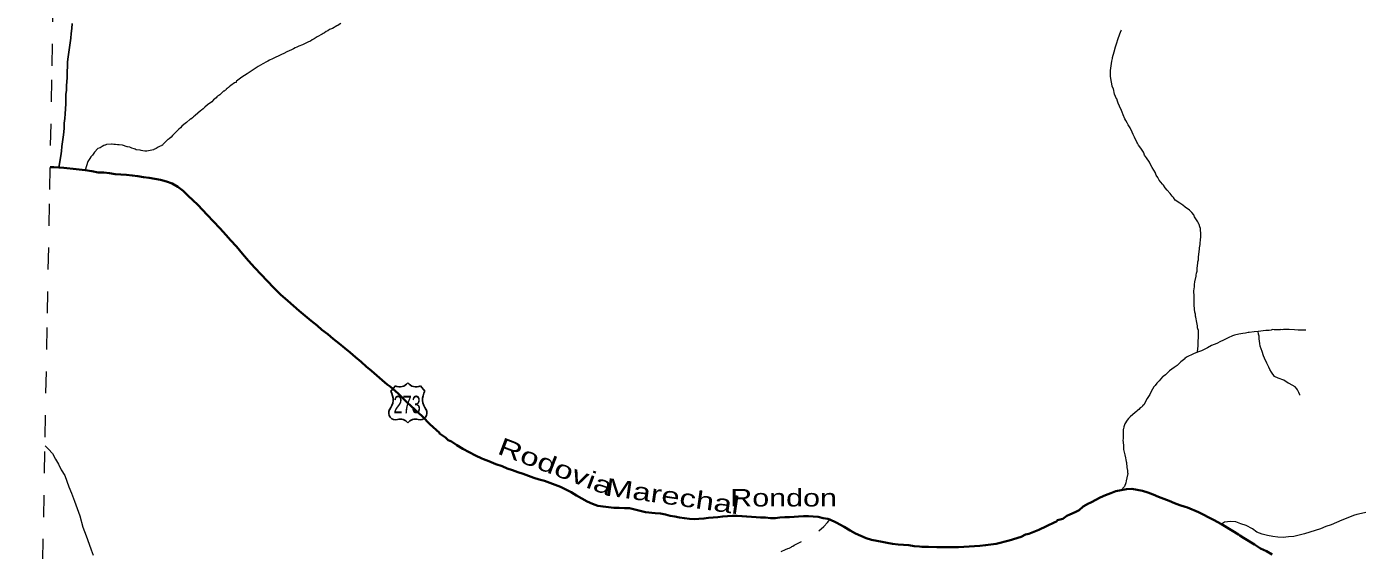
# Model space of a CAD drawing. Extents: x 781.9 to 808.1, y 7453.3 to 7481.5.
# Drawn here: x 781.91 to 787.99, y 7457.81 to 7460.2 of the extents above; entities that cross this region are included whole.
import ezdxf
from ezdxf.enums import TextEntityAlignment as Align

# ---------------------------------------------------------------- set-up
doc = ezdxf.new("R2010")
doc.units = 0
doc.header["$LTSCALE"] = 0.032
for name, pattern in [('DOTTED', [1.5, 0.3, -1.2]), ('LONG_DASHED', [7.5, 6, -1.5]), ('SHORT_DASHED', [2.7, 1.5, -1.2])]:
    doc.linetypes.add(name, pattern=pattern)
for name, color, linetype, lineweight in [('12', 7, 'Continuous', 25), ('2', 7, 'Continuous', 35), ('35', 7, 'SHORT_DASHED', 13), ('4', 7, 'LONG_DASHED', 25), ('5', 7, 'LONG_DASHED', 13), ('7', 7, 'DOTTED', 13)]:
    doc.layers.add(name, color=color, linetype=linetype, lineweight=lineweight)
doc.layers.add('61', color=7, linetype='Continuous')

msp = doc.modelspace()

# ---------------------------------------------------------------- linework, layer by layer
at = {"layer": '12'}
for p, q in [((783.5758, 7458.5342), (783.5967, 7458.5585)), ((783.5758, 7458.5342), (783.5967, 7458.5585)), ((783.6538, 7458.5716), (783.6542, 7458.5712)), ((783.6538, 7458.5716), (783.6542, 7458.5712)), ((783.711, 7458.5585), (783.7319, 7458.5345)), ((783.711, 7458.5585), (783.7319, 7458.5345))]:
    msp.add_line(p, q, dxfattribs=at)
for centre, radius, start, end in [((783.6175, 7458.5986), 0.0452, 242.52866, 323.41613), ((783.6175, 7458.5986), 0.0452, 242.52866, 323.41613), ((783.6901, 7458.5986), 0.0452, 217.23651, 297.49117), ((783.6901, 7458.5986), 0.0452, 217.23651, 297.49117), ((783.5126, 7458.496), 0.0738, 320.67544, 31.14191), ((783.5126, 7458.496), 0.0738, 320.67544, 31.14191), ((783.795, 7458.496), 0.0738, 148.68696, 219.32477), ((783.795, 7458.496), 0.0738, 148.68696, 219.32477), ((783.5978, 7458.4344), 0.0316, 151.50035, 286.50661), ((783.5978, 7458.4344), 0.0316, 151.50035, 286.50661), ((783.7099, 7458.4344), 0.0316, 253.49417, 28.49965), ((783.7099, 7458.4344), 0.0316, 253.49417, 28.49965), ((783.6198, 7458.3627), 0.0433, 38.34716, 107.68663), ((783.6198, 7458.3627), 0.0433, 38.34716, 107.68663), ((783.6878, 7458.3627), 0.0433, 72.31281, 141.65284), ((783.6878, 7458.3627), 0.0433, 72.31281, 141.65284)]:
    msp.add_arc(centre, radius, start, end, dxfattribs=at)
at = {"layer": '2'}
msp.add_line((786.8894, 7458.0772), (786.9137, 7458.082), dxfattribs=at)
for points in [[(782.0194, 7459.5565), (782.0367, 7459.5559), (782.059, 7459.5551)], [(782.059, 7459.5551), (782.0824, 7459.5527), (782.1377, 7459.5471), (782.1794, 7459.5423)], [(782.1794, 7459.5423), (782.2098, 7459.5375), (782.2389, 7459.5325), (782.2648, 7459.5317), (782.2907, 7459.5293), (782.3167, 7459.5244), (782.3426, 7459.5228), (782.3686, 7459.5211), (782.3945, 7459.5187), (782.4205, 7459.5155), (782.4464, 7459.5106), (782.4724, 7459.5073), (782.4983, 7459.5025), (782.5242, 7459.4992), (782.5502, 7459.4903), (782.5761, 7459.4814), (782.6021, 7459.466), (782.6264, 7459.4482), (782.6499, 7459.4262), (782.6718, 7459.4052), (782.6945, 7459.3841), (782.7156, 7459.3614), (782.7366, 7459.3387), (782.765, 7459.3087), (782.795, 7459.2779), (782.8242, 7459.2455), (782.8429, 7459.2236), (782.8712, 7459.1936), (782.898, 7459.1611), (782.9255, 7459.1287), (782.9539, 7459.0971), (782.9831, 7459.0671), (783.0115, 7459.0371), (783.0407, 7459.0055), (783.0723, 7458.9755), (783.1047, 7458.9463), (783.1307, 7458.9228), (783.1575, 7458.9009), (783.1849, 7458.8782), (783.2126, 7458.8547), (783.2393, 7458.8336), (783.2612, 7458.8142), (783.288, 7458.7939), (783.3123, 7458.772), (783.3407, 7458.7517), (783.3658, 7458.7306), (783.3909, 7458.7104), (783.4153, 7458.6893), (783.4404, 7458.6682), (783.4639, 7458.6471), (783.4882, 7458.626), (783.5125, 7458.6049), (783.5361, 7458.5839), (783.5596, 7458.5636), (783.5725, 7458.5547), (783.6094, 7458.5227), (783.651, 7458.4827), (783.7207, 7458.4187), (783.7544, 7458.3835), (783.7985, 7458.3443), (783.7988, 7458.3398), (783.8263, 7458.322), (783.8385, 7458.3107), (783.8539, 7458.3034), (783.8774, 7458.2871), (783.9058, 7458.2709), (783.9342, 7458.2547), (783.9625, 7458.2401), (783.9917, 7458.2271), (783.999, 7458.2239), (784.0233, 7458.2142), (784.0566, 7458.2012), (784.0842, 7458.1907), (784.1085, 7458.1809), (784.1328, 7458.1728), (784.1571, 7458.1647), (784.1814, 7458.1558), (784.2058, 7458.1469), (784.2301, 7458.138), (784.2544, 7458.1307), (784.2787, 7458.1242), (784.3031, 7458.1145), (784.3274, 7458.1063), (784.3517, 7458.0966), (784.376, 7458.0853), (784.4004, 7458.0723), (784.4247, 7458.0577), (784.449, 7458.0431), (784.4733, 7458.0293), (784.4976, 7458.0188)], [(785.5816, 7457.9475), (785.6112, 7457.9339), (785.648, 7457.9147), (785.6749, 7457.8972), (785.6992, 7457.8834), (785.7235, 7457.8728), (785.7478, 7457.8623), (785.7722, 7457.855), (785.7965, 7457.8502), (785.8208, 7457.8453), (785.8451, 7457.8412), (785.8695, 7457.8364), (785.8954, 7457.8339), (785.9197, 7457.8323), (785.944, 7457.8299), (785.9684, 7457.8266), (785.9927, 7457.8242), (786.0032, 7457.8234), (786.0332, 7457.8226), (786.0721, 7457.821), (786.0965, 7457.8209), (786.1208, 7457.8218), (786.1451, 7457.8218), (786.1711, 7457.8218), (786.1954, 7457.8234), (786.2197, 7457.825), (786.244, 7457.8266), (786.2684, 7457.8274), (786.2943, 7457.8299), (786.3186, 7457.8339), (786.3429, 7457.8364), (786.4014, 7457.8524), (786.4575, 7457.8684), (786.4767, 7457.8801), (786.4921, 7457.8818), (786.5375, 7457.9012), (786.5724, 7457.9175), (786.6105, 7457.9361), (786.6186, 7457.9385), (786.6234, 7457.9442), (786.6469, 7457.9515), (786.6656, 7457.9644), (786.6786, 7457.9709), (786.7029, 7457.9807), (786.7216, 7457.9897), (786.7402, 7458.0066), (786.7645, 7458.0204), (786.7726, 7458.0236), (786.7775, 7458.0269), (786.7977, 7458.0374), (786.8181, 7458.048), (786.8424, 7458.0585), (786.8659, 7458.0682), (786.8894, 7458.0772)], [(786.9137, 7458.082), (786.938, 7458.0861), (786.9624, 7458.0877), (786.9867, 7458.0828), (787.011, 7458.0788), (787.0353, 7458.0707)], [(787.0353, 7458.0707), (787.0597, 7458.0617), (787.084, 7458.052), (787.1083, 7458.0423), (787.1326, 7458.0334), (787.1569, 7458.0229), (787.1813, 7458.0131), (787.2056, 7458.0058), (787.2164, 7458.003), (787.2669, 7457.9807), (787.335, 7457.947), (787.373, 7457.9264)], [(784.4976, 7458.0188), (784.522, 7458.0107), (784.5463, 7458.0066), (784.5706, 7458.0042), (784.5949, 7458.0018), (784.6193, 7458.0018), (784.6436, 7458.0001)], [(784.6436, 7458.0001), (784.6674, 7457.9993), (784.6971, 7457.9913), (784.7395, 7457.9809), (784.7844, 7457.9769), (784.809, 7457.9758), (784.8317, 7457.971), (784.8528, 7457.9653), (784.8738, 7457.962), (784.8949, 7457.9572), (784.9176, 7457.9539), (784.9403, 7457.9515), (784.9631, 7457.9499), (784.9841, 7457.9515), (785.0068, 7457.9523), (785.0279, 7457.9547), (785.049, 7457.9563), (785.07, 7457.9588), (785.0927, 7457.962), (785.1154, 7457.9629), (785.1381, 7457.9645), (785.1592, 7457.9645), (785.1803, 7457.9637), (785.203, 7457.9612), (785.2241, 7457.9596), (785.2452, 7457.958), (785.2662, 7457.9572), (785.289, 7457.9564), (785.3117, 7457.9539), (785.3327, 7457.9539), (785.3538, 7457.9564), (785.3765, 7457.958), (785.3976, 7457.9588), (785.4187, 7457.9604), (785.4398, 7457.962), (785.4625, 7457.9629), (785.4852, 7457.9637), (785.5062, 7457.962), (785.5289, 7457.9604), (785.5516, 7457.9539), (785.5727, 7457.9507), (785.5816, 7457.9475)], [(787.373, 7457.9264), (787.4232, 7457.8966), (787.4504, 7457.879), (787.4561, 7457.8753), (787.4731, 7457.8639), (787.5234, 7457.8331), (787.551, 7457.8161), (787.5785, 7457.8039), (787.6045, 7457.7877)]]:
    msp.add_lwpolyline(points, dxfattribs=at)
at = {"layer": '35'}
msp.add_lwpolyline([(781.9116, 7453.8021), (781.9222, 7454.3673), (781.9328, 7454.9326), (781.9434, 7455.4979), (781.954, 7456.0631), (781.9646, 7456.6284), (781.9752, 7457.1936), (781.9858, 7457.7589), (781.9964, 7458.3241), (782.0069, 7458.8894), (782.0175, 7459.4547), (782.0281, 7460.0199), (782.0387, 7460.5852)], dxfattribs=at)
at = {"layer": '4'}
msp.add_lwpolyline([(782.1205, 7460.2119), (782.118, 7460.1892), (782.1156, 7460.1665), (782.1132, 7460.1454), (782.1099, 7460.1244), (782.1075, 7460.1033), (782.1043, 7460.0822), (782.1018, 7460.0595), (782.0986, 7460.0368), (782.0978, 7460.0157), (782.0962, 7459.9938), (782.0962, 7459.9638), (782.0945, 7459.9298), (782.0937, 7459.9087), (782.0913, 7459.8876), (782.0913, 7459.8665), (782.0905, 7459.8455), (782.0896, 7459.8228), (782.0872, 7459.8001), (782.0856, 7459.779), (782.0832, 7459.7579), (782.0832, 7459.7368), (782.0824, 7459.7157), (782.0791, 7459.693), (782.0759, 7459.672), (782.0726, 7459.6509), (782.071, 7459.6298), (782.0678, 7459.6087), (782.059, 7459.5551)], dxfattribs=at)
at = {"layer": '5'}
for points in [[(781.9957, 7458.2848), (782.0115, 7458.2695), (782.0299, 7458.2495), (782.0443, 7458.2231), (782.0572, 7458.2012), (782.0702, 7458.1753), (782.0856, 7458.1493), (782.0953, 7458.1234), (782.105, 7458.0974), (782.1167, 7458.0676), (782.1303, 7458.0308), (782.1543, 7457.9644), (782.1687, 7457.9124), (782.1831, 7457.8732), (782.1975, 7457.8348), (782.2072, 7457.8088), (782.2161, 7457.7845)], [(788.0399, 7457.981), (787.9911, 7457.9714), (787.9751, 7457.9666), (787.9503, 7457.9554), (787.9223, 7457.945), (787.898, 7457.9345), (787.8737, 7457.9239), (787.8493, 7457.9158), (787.825, 7457.9053), (787.8007, 7457.898), (787.7764, 7457.8899), (787.7521, 7457.8818), (787.7277, 7457.8761), (787.7034, 7457.8704), (787.6791, 7457.868), (787.6548, 7457.8664), (787.6304, 7457.8672), (787.6062, 7457.8704), (787.5818, 7457.8753), (787.5575, 7457.881), (787.5331, 7457.8907), (787.5137, 7457.9045), (787.4845, 7457.9199), (787.461, 7457.9288), (787.4378, 7457.9376), (787.413, 7457.9384), (787.3858, 7457.936), (787.373, 7457.9264)]]:
    msp.add_lwpolyline(points, dxfattribs=at)
at = {"layer": '7'}
for points in [[(783.288, 7460.1794), (783.2799, 7460.1754), (783.2734, 7460.1697), (783.2669, 7460.1665), (783.2628, 7460.1641), (783.2393, 7460.1511), (783.2264, 7460.143), (783.2166, 7460.1381), (783.2085, 7460.1324), (783.2004, 7460.1292), (783.1964, 7460.1268), (783.1729, 7460.1146), (783.155, 7460.1089), (783.1469, 7460.1049), (783.1388, 7460.1016), (783.1307, 7460.0966), (783.1218, 7460.0927), (783.1007, 7460.083), (783.0869, 7460.0757), (783.0772, 7460.0716), (783.0675, 7460.0659), (783.0577, 7460.0619), (783.0537, 7460.0603), (783.035, 7460.0505), (783.0221, 7460.0449), (783.0139, 7460.04), (783.0042, 7460.036), (782.9945, 7460.0303), (782.9904, 7460.0287), (782.9693, 7460.0157), (782.9556, 7460.0076), (782.9191, 7459.9831), (782.895, 7459.9671), (782.8705, 7459.9491), (782.8688, 7459.9468), (782.8688, 7459.9435), (782.8663, 7459.9427), (782.8623, 7459.9411), (782.8453, 7459.9289), (782.838, 7459.9232), (782.8347, 7459.9208), (782.8315, 7459.9184), (782.8283, 7459.9152), (782.8242, 7459.9119), (782.8234, 7459.9111), (782.8209, 7459.9087), (782.8177, 7459.9062), (782.8145, 7459.903), (782.8113, 7459.903), (782.8104, 7459.9022), (782.7942, 7459.8868), (782.7902, 7459.8844), (782.7877, 7459.8827), (782.7845, 7459.8811), (782.7812, 7459.8771), (782.7772, 7459.8738), (782.7658, 7459.8632), (782.7577, 7459.8544), (782.7383, 7459.8414), (782.7261, 7459.8308), (782.7188, 7459.8235), (782.7107, 7459.817), (782.7067, 7459.813), (782.6937, 7459.8025), (782.6815, 7459.7927), (782.675, 7459.787), (782.6694, 7459.7814), (782.6621, 7459.7764), (782.6596, 7459.7749), (782.6418, 7459.7611), (782.6296, 7459.7506), (782.6215, 7459.7433), (782.6142, 7459.736), (782.6077, 7459.7295), (782.5899, 7459.7125), (782.5785, 7459.7011), (782.5721, 7459.6938), (782.5631, 7459.6857), (782.5583, 7459.6825), (782.5559, 7459.6809), (782.5348, 7459.6598), (782.5332, 7459.6565), (782.5283, 7459.6557), (782.5283, 7459.6541), (782.5226, 7459.6517), (782.5129, 7459.6476), (782.5032, 7459.6419), (782.4934, 7459.6371), (782.491, 7459.6363), (782.4756, 7459.6322), (782.461, 7459.6297), (782.4513, 7459.6289), (782.4432, 7459.6306), (782.4351, 7459.633), (782.431, 7459.6338)], [(783.348, 7460.2127), (783.3407, 7460.2078), (783.3334, 7460.2038), (783.3293, 7460.2022), (783.3099, 7460.19), (783.2961, 7460.1843), (783.288, 7460.1794)], [(787.1472, 7459.4239), (787.1375, 7459.436), (787.1237, 7459.4522), (787.1156, 7459.4628), (787.1066, 7459.4741), (787.1026, 7459.4782), (787.088, 7459.4968), (787.0807, 7459.5098), (787.0742, 7459.5195), (787.0702, 7459.5293), (787.0702, 7459.5301), (787.0556, 7459.5544), (787.0483, 7459.5682), (787.045, 7459.5763), (787.0434, 7459.5787), (787.0288, 7459.599), (787.0207, 7459.612), (787.0167, 7459.6217), (787.0151, 7459.6257), (787.0029, 7459.6436), (786.9931, 7459.6574), (786.9891, 7459.6655), (786.9859, 7459.6711), (786.9753, 7459.693), (786.9688, 7459.706), (786.9648, 7459.7157), (786.9648, 7459.7165), (786.9542, 7459.7361), (786.9461, 7459.7498), (786.9412, 7459.7595), (786.9348, 7459.7692), (786.9307, 7459.7765), (786.9234, 7459.7952), (786.9185, 7459.8073), (786.9153, 7459.8154), (786.9056, 7459.8357), (786.9007, 7459.8487), (786.8967, 7459.8584), (786.8934, 7459.8682), (786.8926, 7459.869), (786.8829, 7459.89), (786.878, 7459.9136), (786.8732, 7459.9249), (786.8724, 7459.9273), (786.869, 7459.9446), (786.8646, 7459.9699), (786.8654, 7459.9971), (786.8706, 7460.0408), (786.874, 7460.053), (786.8748, 7460.0571), (786.8812, 7460.0838), (786.8861, 7460.1), (786.8862, 7460.1008), (786.8942, 7460.1244), (786.8991, 7460.1398), (786.9072, 7460.1649), (786.9137, 7460.1803), (786.9153, 7460.1835)], [(782.3734, 7459.6492), (782.371, 7459.6493), (782.3491, 7459.6565), (782.3345, 7459.6589), (782.3264, 7459.6589), (782.3183, 7459.6606), (782.3102, 7459.6606), (782.3021, 7459.6614), (782.2997, 7459.6622), (782.2762, 7459.6598), (782.2729, 7459.6582), (782.2712, 7459.6573), (782.2688, 7459.6565), (782.2648, 7459.6549), (782.2567, 7459.6508), (782.247, 7459.6452), (782.2372, 7459.6419), (782.2364, 7459.6411), (782.2218, 7459.6249), (782.2121, 7459.612), (782.2048, 7459.603), (782.2007, 7459.5965), (782.191, 7459.5828), (782.1794, 7459.5423)], [(782.431, 7459.6338), (782.4124, 7459.6362), (782.4075, 7459.6387), (782.4026, 7459.6403), (782.3929, 7459.6435), (782.3832, 7459.6476), (782.3734, 7459.6492)], [(787.2064, 7459.3744), (787.195, 7459.3825), (787.1821, 7459.3922), (787.161, 7459.4052), (787.1602, 7459.406), (787.1529, 7459.4174), (787.1472, 7459.4239)], [(787.2627, 7458.7118), (787.2639, 7458.7282), (787.2664, 7458.7396), (787.2656, 7458.7598), (787.2664, 7458.7655), (787.2672, 7458.7752), (787.2672, 7458.7882), (787.2672, 7458.8133), (787.2664, 7458.8142), (787.2631, 7458.8223), (787.2623, 7458.8328), (787.2591, 7458.8466), (787.255, 7458.8717), (787.2542, 7458.8758), (787.2534, 7458.8855), (787.251, 7458.8952), (787.2485, 7458.9082), (787.2478, 7458.9285), (787.2477, 7458.9358), (787.2469, 7458.9439), (787.2469, 7458.952), (787.2469, 7458.9666), (787.2453, 7458.9917), (787.2469, 7459.0006), (787.2485, 7459.0104), (787.2493, 7459.0201), (787.251, 7459.0331), (787.2559, 7459.0582), (787.2566, 7459.0639), (787.2574, 7459.072), (787.2607, 7459.0817), (787.2615, 7459.0947), (787.264, 7459.1182), (787.2647, 7459.1239), (787.2672, 7459.1336), (787.2672, 7459.1465), (787.2705, 7459.1701), (787.2704, 7459.1725), (787.272, 7459.1806), (787.272, 7459.1887), (787.2745, 7459.2033), (787.2769, 7459.2301), (787.2777, 7459.2341), (787.2785, 7459.2471), (787.2761, 7459.2771), (787.2729, 7459.2844), (787.2696, 7459.2941), (787.268, 7459.2966), (787.2672, 7459.3006), (787.2639, 7459.3063), (787.2494, 7459.329), (787.2494, 7459.3298), (787.2453, 7459.3395), (787.2372, 7459.3492), (787.2259, 7459.3597), (787.2064, 7459.3744)], [(787.5393, 7458.806), (787.5218, 7458.8044), (787.4983, 7458.8012), (787.4942, 7458.8011), (787.4813, 7458.7987), (787.4699, 7458.7971), (787.4521, 7458.7939), (787.4318, 7458.789), (787.4229, 7458.7857), (787.4034, 7458.7776), (787.3783, 7458.7647), (787.3677, 7458.7598), (787.3515, 7458.7517), (787.3264, 7458.742), (787.3076, 7458.731), (787.2812, 7458.7182), (787.2627, 7458.7118)], [(787.7577, 7458.8125), (787.7456, 7458.8125), (787.7342, 7458.8125), (787.7229, 7458.8125), (787.7066, 7458.8142), (787.6815, 7458.8158), (787.6758, 7458.8158), (787.6661, 7458.8157), (787.6564, 7458.8149), (787.6499, 7458.8141), (787.6442, 7458.815), (787.6402, 7458.8142), (787.615, 7458.8142), (787.6126, 7458.8141), (787.6036, 7458.8149), (787.6012, 7458.8141), (787.6012, 7458.8125), (787.5899, 7458.8109), (787.5785, 7458.8109), (787.5745, 7458.8109), (787.5393, 7458.806)], [(787.731, 7458.515), (787.7301, 7458.5174), (787.7261, 7458.5272), (787.7196, 7458.5393), (787.7162, 7458.5441), (787.7082, 7458.5531), (787.6815, 7458.5685), (787.6775, 7458.5709), (787.6568, 7458.5833), (787.6311, 7458.5929), (787.6142, 7458.6009), (787.601, 7458.6206), (787.5931, 7458.6334), (787.5882, 7458.6439), (787.5801, 7458.6617), (787.5688, 7458.6852), (787.5647, 7458.6958), (787.5582, 7458.7153), (787.5494, 7458.7388), (787.5477, 7458.7509), (787.5449, 7458.773), (787.5437, 7458.785), (787.5409, 7458.7939), (787.5393, 7458.806)], [(787.2627, 7458.7118), (787.2438, 7458.7049), (787.2121, 7458.6885), (787.205, 7458.6829), (787.204, 7458.682), (787.1861, 7458.6674), (787.178, 7458.6585), (787.1699, 7458.6512), (787.1561, 7458.6414), (787.1342, 7458.6269), (787.1261, 7458.6179), (787.1164, 7458.6082), (787.105, 7458.6001), (787.1026, 7458.5985), (787.0872, 7458.5806), (787.0767, 7458.5701), (787.0685, 7458.5596), (787.0637, 7458.5539), (787.0507, 7458.5328), (787.0442, 7458.519), (787.0385, 7458.5093), (787.0329, 7458.5004), (787.0167, 7458.472), (787.0118, 7458.4663), (787.011, 7458.4647), (787.0069, 7458.4607), (787.0013, 7458.4574), (786.9948, 7458.4501), (786.9883, 7458.4452), (786.9859, 7458.442), (786.9672, 7458.4266), (786.9551, 7458.416), (786.9478, 7458.4087), (786.9405, 7458.4015), (786.9307, 7458.3845), (786.9266, 7458.3715), (786.9242, 7458.3618), (786.9234, 7458.3593), (786.9226, 7458.3309), (786.9226, 7458.3164), (786.9218, 7458.3107), (786.9242, 7458.2872), (786.925, 7458.2742), (786.9251, 7458.2669), (786.9307, 7458.2434), (786.934, 7458.2288), (786.9348, 7458.2207), (786.9372, 7458.2126), (786.938, 7458.2085), (786.9396, 7458.185), (786.9421, 7458.172), (786.9429, 7458.1623), (786.9437, 7458.1582), (786.9396, 7458.138), (786.9372, 7458.125), (786.9356, 7458.1153), (786.9296, 7458.0981), (786.9137, 7458.082)], [(785.5325, 7457.8967), (785.5548, 7457.9158), (785.5721, 7457.9347), (785.5816, 7457.9475)], [(785.3595, 7457.8023), (785.3798, 7457.8104), (785.3902, 7457.8161), (785.396, 7457.8177), (785.4057, 7457.8217), (785.4073, 7457.8234), (785.4089, 7457.8242), (785.413, 7457.8266), (785.4195, 7457.8299), (785.4434, 7457.8428), (785.4524, 7457.8481)]]:
    msp.add_lwpolyline(points, dxfattribs=at)

# ---------------------------------------------------------------- texts
at = {"layer": '61'}
for s, width, p in [('273', 0.7, (783.6505, 7458.433)), ('Rondon', 1.3, (785.3711, 7458.0072))]:
    msp.add_text(s, height=0.08, dxfattribs=dict(at, width=width)).set_placement(p, align=Align.CENTER)
at = {"layer": '61', "width": 1.4}
for s, rotation, p in [('Rodovia', 339.176, (784.3154, 7458.1521)), ('Marechal', 351.87, (784.8581, 7458.0151))]:
    msp.add_text(s, height=0.08, rotation=rotation, dxfattribs=at).set_placement(p, align=Align.CENTER)

doc.saveas('drawing.dxf')
